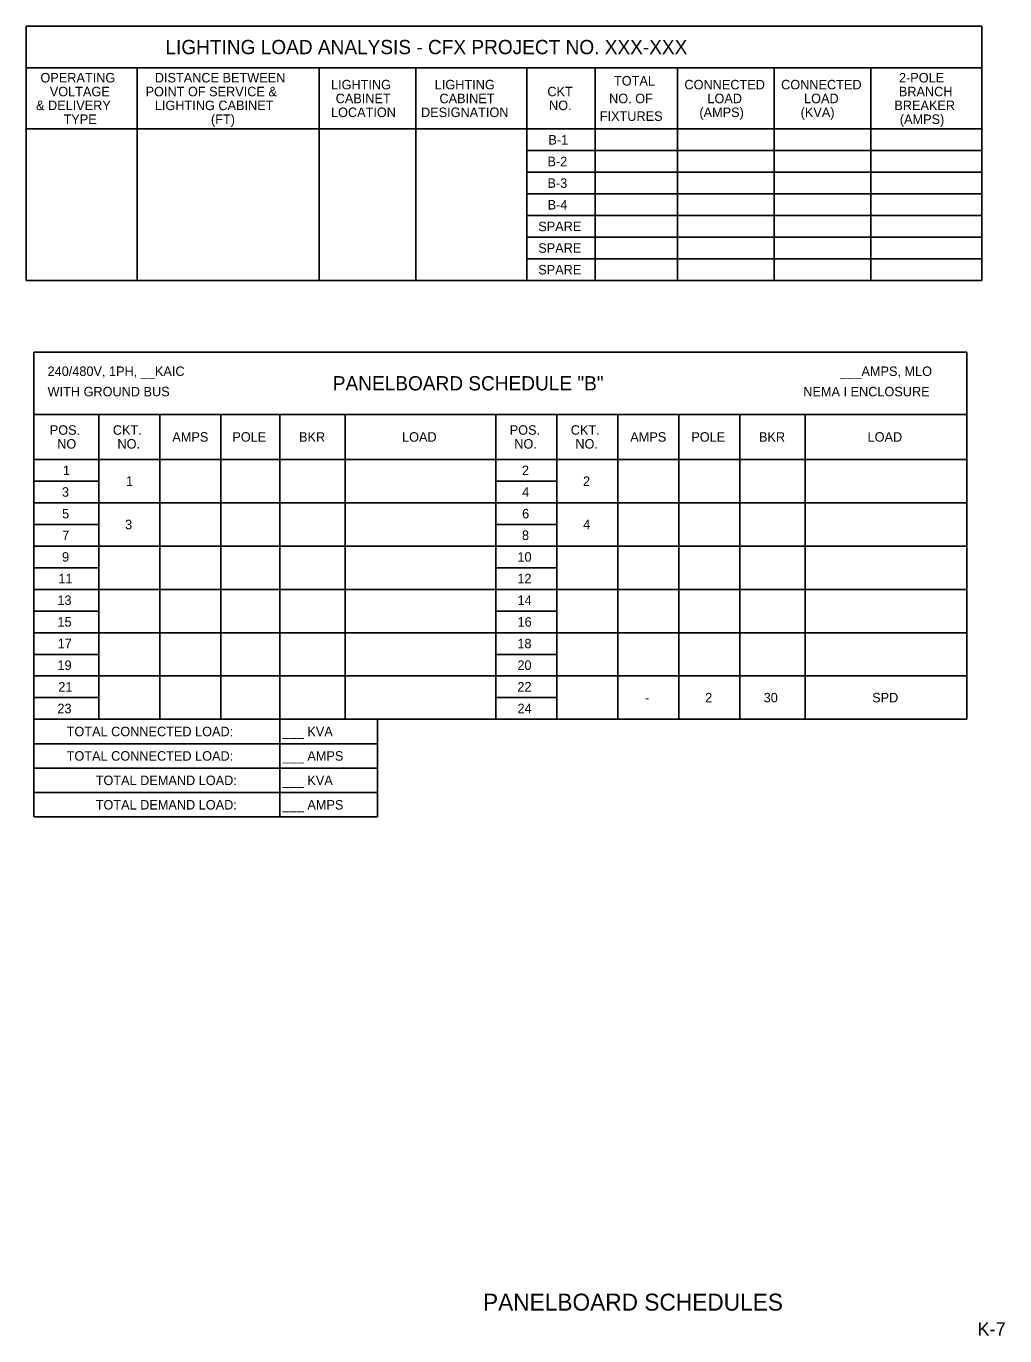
# Model space of a CAD drawing. Extents: x 856079 to 2148480, y 462635 to 2147771.
# Drawn here: x 2148473.14 to 2148480.35, y 2147761.82 to 2147771.47 of the extents above; entities that cross this region are included whole.
import ezdxf

# ---------------------------------------------------------------- set-up
doc = ezdxf.new("R2010")
doc.units = 0
for name, color, linetype in [('FLMap5', 7, 'Continuous'), ('NonPlottingEle_dp', 7, 'Continuous'), ('SignPanel', 7, 'Continuous'), ('SumBoxBorder_dp', 7, 'Continuous'), ('SumBoxLines_dp', 7, 'Continuous')]:
    doc.layers.add(name, color=color, linetype=linetype)

msp = doc.modelspace()

# ---------------------------------------------------------------- linework, layer by layer
at = {"layer": 'SumBoxBorder_dp'}
for p, q in [((2148473.1374, 2147771.4724), (2148480.1799, 2147771.4724)), ((2148473.1374, 2147771.4724), (2148473.1374, 2147769.5984)), ((2148480.1799, 2147771.4724), (2148480.1799, 2147769.5984)), ((2148473.1374, 2147771.1649), (2148480.1799, 2147771.1649)), ((2148473.1374, 2147771.1649), (2148480.1799, 2147771.1649)), ((2148473.1374, 2147769.5984), (2148480.1799, 2147769.5984)), ((2148473.1927, 2147769.0699), (2148480.0702, 2147769.0699)), ((2148473.1927, 2147769.0699), (2148473.1927, 2147765.6454)), ((2148480.0702, 2147769.0699), (2148480.0702, 2147766.3654)), ((2148473.1927, 2147768.6124), (2148480.0702, 2147768.6124)), ((2148473.1927, 2147768.6124), (2148480.0702, 2147768.6124)), ((2148473.1927, 2147766.3654), (2148480.0702, 2147766.3654)), ((2148473.1927, 2147766.3654), (2148480.0702, 2147766.3654)), ((2148475.0077, 2147766.3654), (2148475.0077, 2147765.6454)), ((2148475.7277, 2147766.3654), (2148475.7277, 2147765.6454)), ((2148475.7277, 2147766.3654), (2148475.7277, 2147765.6454)), ((2148473.1927, 2147766.1854), (2148475.7277, 2147766.1854)), ((2148473.1927, 2147766.1854), (2148475.7277, 2147766.1854)), ((2148473.1927, 2147766.0054), (2148475.7277, 2147766.0054)), ((2148473.1927, 2147766.0054), (2148475.7277, 2147766.0054)), ((2148473.1927, 2147765.8254), (2148475.7277, 2147765.8254)), ((2148473.1927, 2147765.8254), (2148475.7277, 2147765.8254)), ((2148473.1927, 2147765.6454), (2148475.7277, 2147765.6454))]:
    msp.add_line(p, q, dxfattribs=at)
at = {"layer": 'SumBoxLines_dp'}
for p, q in [((2148473.9549, 2147771.1649), (2148473.9549, 2147769.5984)), ((2148473.9549, 2147771.1649), (2148473.9549, 2147769.5984)), ((2148475.2974, 2147771.1649), (2148475.2974, 2147769.5984)), ((2148475.2974, 2147771.1649), (2148475.2974, 2147769.5984)), ((2148476.0099, 2147771.1649), (2148476.0099, 2147769.5984)), ((2148476.0099, 2147771.1649), (2148476.0099, 2147769.5984)), ((2148476.8274, 2147771.1649), (2148476.8274, 2147769.5984)), ((2148476.8274, 2147771.1649), (2148476.8274, 2147769.5984)), ((2148477.3299, 2147771.1649), (2148477.3299, 2147769.5984)), ((2148477.3299, 2147771.1649), (2148477.3299, 2147769.5984)), ((2148477.9374, 2147771.1649), (2148477.9374, 2147769.5984)), ((2148477.9374, 2147771.1649), (2148477.9374, 2147769.5984)), ((2148478.6499, 2147771.1649), (2148478.6499, 2147769.5984)), ((2148478.6499, 2147771.1649), (2148478.6499, 2147769.5984)), ((2148479.3624, 2147771.1649), (2148479.3624, 2147769.5984)), ((2148479.3624, 2147771.1649), (2148479.3624, 2147769.5984)), ((2148473.1374, 2147770.7149), (2148480.1799, 2147770.7149)), ((2148473.1374, 2147770.7149), (2148480.1799, 2147770.7149)), ((2148476.8274, 2147770.5554), (2148480.1799, 2147770.5554)), ((2148476.8274, 2147770.5554), (2148480.1799, 2147770.5554)), ((2148476.8274, 2147770.3959), (2148480.1799, 2147770.3959)), ((2148476.8274, 2147770.3959), (2148480.1799, 2147770.3959)), ((2148476.8274, 2147770.2364), (2148480.1799, 2147770.2364)), ((2148476.8274, 2147770.2364), (2148480.1799, 2147770.2364)), ((2148476.8274, 2147770.0769), (2148480.1799, 2147770.0769)), ((2148476.8274, 2147770.0769), (2148480.1799, 2147770.0769)), ((2148476.8274, 2147769.9174), (2148480.1799, 2147769.9174)), ((2148476.8274, 2147769.9174), (2148480.1799, 2147769.9174)), ((2148476.8274, 2147769.7579), (2148480.1799, 2147769.7579)), ((2148476.8274, 2147769.7579), (2148480.1799, 2147769.7579)), ((2148473.6727, 2147768.6124), (2148473.6727, 2147766.3654)), ((2148473.6727, 2147768.6124), (2148473.6727, 2147766.3654)), ((2148474.1227, 2147768.6124), (2148474.1227, 2147766.3654)), ((2148474.1227, 2147768.6124), (2148474.1227, 2147766.3654)), ((2148474.5727, 2147768.6124), (2148474.5727, 2147766.3654)), ((2148474.5727, 2147768.6124), (2148474.5727, 2147766.3654)), ((2148475.0077, 2147768.6124), (2148475.0077, 2147766.3654)), ((2148475.0077, 2147768.6124), (2148475.0077, 2147766.3654)), ((2148475.4877, 2147768.6124), (2148475.4877, 2147766.3654)), ((2148475.4877, 2147768.6124), (2148475.4877, 2147766.3654)), ((2148476.5977, 2147768.6124), (2148476.5977, 2147766.3654)), ((2148476.5977, 2147768.6124), (2148476.5977, 2147766.3654)), ((2148477.0477, 2147768.6124), (2148477.0477, 2147766.3654)), ((2148477.0477, 2147768.6124), (2148477.0477, 2147766.3654)), ((2148477.4977, 2147768.6124), (2148477.4977, 2147766.3654)), ((2148477.4977, 2147768.6124), (2148477.4977, 2147766.3654)), ((2148477.9477, 2147768.6124), (2148477.9477, 2147766.3654)), ((2148477.9477, 2147768.6124), (2148477.9477, 2147766.3654)), ((2148478.3977, 2147768.6124), (2148478.3977, 2147766.3654)), ((2148478.3977, 2147768.6124), (2148478.3977, 2147766.3654)), ((2148478.8777, 2147768.6124), (2148478.8777, 2147766.3654)), ((2148478.8777, 2147768.6124), (2148478.8777, 2147766.3654)), ((2148473.1927, 2147768.2794), (2148480.0702, 2147768.2794)), ((2148473.1927, 2147768.2794), (2148480.0702, 2147768.2794)), ((2148473.1927, 2147768.1199), (2148473.6727, 2147768.1199)), ((2148473.1927, 2147768.1199), (2148473.6727, 2147768.1199)), ((2148476.5977, 2147768.1199), (2148477.0477, 2147768.1199)), ((2148473.1927, 2147767.9604), (2148480.0702, 2147767.9604)), ((2148473.1927, 2147767.9604), (2148480.0702, 2147767.9604)), ((2148473.1927, 2147767.8009), (2148473.6727, 2147767.8009)), ((2148473.1927, 2147767.8009), (2148473.6727, 2147767.8009)), ((2148476.5977, 2147767.8009), (2148477.0477, 2147767.8009)), ((2148476.5977, 2147767.8009), (2148477.0477, 2147767.8009)), ((2148473.1927, 2147767.6414), (2148476.5977, 2147767.6414)), ((2148473.1927, 2147767.6414), (2148480.0702, 2147767.6414)), ((2148477.0477, 2147767.6414), (2148480.0702, 2147767.6414)), ((2148473.1927, 2147767.4819), (2148473.6727, 2147767.4819)), ((2148473.1927, 2147767.4819), (2148473.6727, 2147767.4819)), ((2148476.5977, 2147767.4819), (2148477.0477, 2147767.4819)), ((2148476.5977, 2147767.4819), (2148477.0477, 2147767.4819)), ((2148473.1927, 2147767.3224), (2148480.0702, 2147767.3224)), ((2148473.1927, 2147767.3224), (2148480.0702, 2147767.3224)), ((2148473.1927, 2147767.1629), (2148473.6727, 2147767.1629)), ((2148473.1927, 2147767.1629), (2148473.6727, 2147767.1629)), ((2148476.5977, 2147767.1629), (2148477.0477, 2147767.1629)), ((2148473.1927, 2147767.0034), (2148480.0702, 2147767.0034)), ((2148473.1927, 2147767.0034), (2148480.0702, 2147767.0034)), ((2148473.1927, 2147766.8439), (2148473.6727, 2147766.8439)), ((2148473.1927, 2147766.8439), (2148473.6727, 2147766.8439)), ((2148476.5977, 2147766.8439), (2148477.0477, 2147766.8439)), ((2148476.5977, 2147766.8439), (2148477.0477, 2147766.8439)), ((2148473.1927, 2147766.6844), (2148476.5977, 2147766.6844)), ((2148473.1927, 2147766.6844), (2148480.0702, 2147766.6844)), ((2148477.0477, 2147766.6844), (2148480.0702, 2147766.6844)), ((2148473.1927, 2147766.5249), (2148473.6727, 2147766.5249)), ((2148473.1927, 2147766.5249), (2148473.6727, 2147766.5249)), ((2148476.5977, 2147766.5249), (2148477.0477, 2147766.5249)), ((2148476.5977, 2147766.5249), (2148477.0477, 2147766.5249))]:
    msp.add_line(p, q, dxfattribs=at)

# ---------------------------------------------------------------- texts
at = {"layer": 'FLMap5'}
for s, height, p in [('LIGHTING LOAD ANALYSIS - CFX PROJECT NO. XXX-XXX', 0.105, (2148474.1638, 2147771.2662)), ('OPERATING', 0.07, (2148473.2425, 2147771.0579)), ('DISTANCE BETWEEN', 0.07, (2148474.0854, 2147771.0579)), ('LIGHTING', 0.07, (2148475.3839, 2147771.0069)), ('LIGHTING', 0.07, (2148476.1489, 2147771.0069)), ('TOTAL', 0.07, (2148477.47, 2147771.0349)), ('CONNECTED', 0.07, (2148477.989, 2147771.0069)), ('CONNECTED', 0.07, (2148478.7015, 2147771.0069)), ('2-POLE', 0.07, (2148479.5701, 2147771.0579)), ('VOLTAGE', 0.07, (2148473.3112, 2147770.9559)), ('POINT OF SERVICE &', 0.07, (2148474.0176, 2147770.9559)), ('CABINET', 0.07, (2148475.4183, 2147770.9049)), ('CABINET', 0.07, (2148476.1833, 2147770.9049)), ('CKT', 0.07, (2148476.9788, 2147770.9559)), ('NO. OF', 0.07, (2148477.4336, 2147770.9049)), ('LOAD', 0.07, (2148478.1584, 2147770.9049)), ('LOAD', 0.07, (2148478.8709, 2147770.9049)), ('BRANCH', 0.07, (2148479.5692, 2147770.9559)), ('& DELIVERY', 0.07, (2148473.2097, 2147770.8539)), ('LIGHTING CABINET', 0.07, (2148474.0859, 2147770.8539)), ('NO.', 0.07, (2148476.991, 2147770.8539)), ('(AMPS)', 0.07, (2148478.099, 2147770.8029)), ('(KVA)', 0.07, (2148478.8454, 2147770.8029)), ('BREAKER', 0.07, (2148479.5362, 2147770.8539)), ('TYPE', 0.07, (2148473.4128, 2147770.7519)), ('(FT)', 0.07, (2148474.4993, 2147770.7519)), ('LOCATION', 0.07, (2148475.3839, 2147770.8029)), ('DESIGNATION', 0.07, (2148476.0473, 2147770.8029)), ('FIXTURES', 0.07, (2148477.365, 2147770.7749)), ('(AMPS)', 0.07, (2148479.5765, 2147770.7519)), ('B-1', 0.07, (2148476.9862, 2147770.6002)), ('B-2', 0.07, (2148476.9795, 2147770.4407)), ('B-3', 0.07, (2148476.9794, 2147770.2812)), ('B-4', 0.07, (2148476.9808, 2147770.1217)), ('SPARE', 0.07, (2148476.9115, 2147769.9622)), ('SPARE', 0.07, (2148476.9115, 2147769.8027)), ('SPARE', 0.07, (2148476.9115, 2147769.6432)), ('240/480V, 1PH, __KAIC', 0.07, (2148473.2952, 2147768.8949)), ('___AMPS, MLO', 0.07, (2148479.1374, 2147768.8949)), ('PANELBOARD SCHEDULE "B"', 0.105, (2148475.3974, 2147768.7887)), ('WITH GROUND BUS', 0.07, (2148473.2952, 2147768.7449)), ('NEMA I ENCLOSURE', 0.07, (2148478.865, 2147768.7449)), ('POS.', 0.07, (2148473.3112, 2147768.4619)), ('CKT.', 0.07, (2148473.7762, 2147768.4619)), ('AMPS', 0.07, (2148474.2146, 2147768.4109)), ('POLE', 0.07, (2148474.6569, 2147768.4109)), ('BKR', 0.07, (2148475.1482, 2147768.4109)), ('LOAD', 0.07, (2148475.9075, 2147768.4109)), ('POS.', 0.07, (2148476.7012, 2147768.4619)), ('CKT.', 0.07, (2148477.1512, 2147768.4619)), ('AMPS', 0.07, (2148477.5896, 2147768.4109)), ('POLE', 0.07, (2148478.0394, 2147768.4109)), ('BKR', 0.07, (2148478.5382, 2147768.4109)), ('LOAD', 0.07, (2148479.3387, 2147768.4109)), ('NO', 0.07, (2148473.3659, 2147768.3599)), ('NO.', 0.07, (2148473.81, 2147768.3599)), ('NO.', 0.07, (2148476.735, 2147768.3599)), ('NO.', 0.07, (2148477.185, 2147768.3599)), ('1', 0.07, (2148473.408, 2147768.1647)), ('2', 0.07, (2148476.7913, 2147768.1647)), ('1', 0.07, (2148473.873, 2147768.0849)), ('2', 0.07, (2148477.2413, 2147768.0849)), ('3', 0.07, (2148473.4013, 2147768.0052)), ('4', 0.07, (2148476.7927, 2147768.0052)), ('5', 0.07, (2148473.4022, 2147767.8457)), ('6', 0.07, (2148476.7927, 2147767.8457)), ('3', 0.07, (2148473.8663, 2147767.7659)), ('4', 0.07, (2148477.2427, 2147767.7659)), ('7', 0.07, (2148473.4033, 2147767.6862)), ('8', 0.07, (2148476.7915, 2147767.6862)), ('9', 0.07, (2148473.4017, 2147767.5267)), ('10', 0.07, (2148476.758, 2147767.5267)), ('11', 0.07, (2148473.3742, 2147767.3672)), ('12', 0.07, (2148476.7574, 2147767.3672)), ('13', 0.07, (2148473.3674, 2147767.2077)), ('14', 0.07, (2148476.7588, 2147767.2077)), ('15', 0.07, (2148473.3683, 2147767.0482)), ('16', 0.07, (2148476.7588, 2147767.0482)), ('17', 0.07, (2148473.3694, 2147766.8887)), ('18', 0.07, (2148476.7577, 2147766.8887)), ('19', 0.07, (2148473.3678, 2147766.7292)), ('20', 0.07, (2148476.758, 2147766.7292)), ('21', 0.07, (2148473.3742, 2147766.5697)), ('22', 0.07, (2148476.7574, 2147766.5697)), ('2', 0.07, (2148478.1413, 2147766.4899)), ('30', 0.07, (2148478.573, 2147766.4899)), ('SPD', 0.07, (2148479.3726, 2147766.4899)), ('23', 0.07, (2148473.3674, 2147766.4102)), ('24', 0.07, (2148476.7588, 2147766.4102)), ('-', 0.07, (2148477.6992, 2147766.4899)), ('TOTAL CONNECTED LOAD:', 0.07, (2148473.4358, 2147766.2404)), ('___ KVA', 0.07, (2148475.0277, 2147766.2404)), ('TOTAL CONNECTED LOAD:', 0.07, (2148473.4358, 2147766.0604)), ('___ AMPS', 0.07, (2148475.0277, 2147766.0604)), ('TOTAL DEMAND LOAD:', 0.07, (2148473.6498, 2147765.8804)), ('___ KVA', 0.07, (2148475.0277, 2147765.8804)), ('TOTAL DEMAND LOAD:', 0.07, (2148473.6498, 2147765.7004)), ('___ AMPS', 0.07, (2148475.0277, 2147765.7004))]:
    msp.add_text(s, height=height, dxfattribs=at).set_placement(p)
at = {"layer": 'NonPlottingEle_dp'}
msp.add_text('K-7', height=0.1, dxfattribs=at).set_placement((2148480.1488, 2147761.8225))
at = {"layer": 'SignPanel'}
msp.add_text('     PANELBOARD SCHEDULES      ', height=0.125, dxfattribs=at).set_placement((2148476.272, 2147762.0082))

doc.saveas('drawing.dxf')
